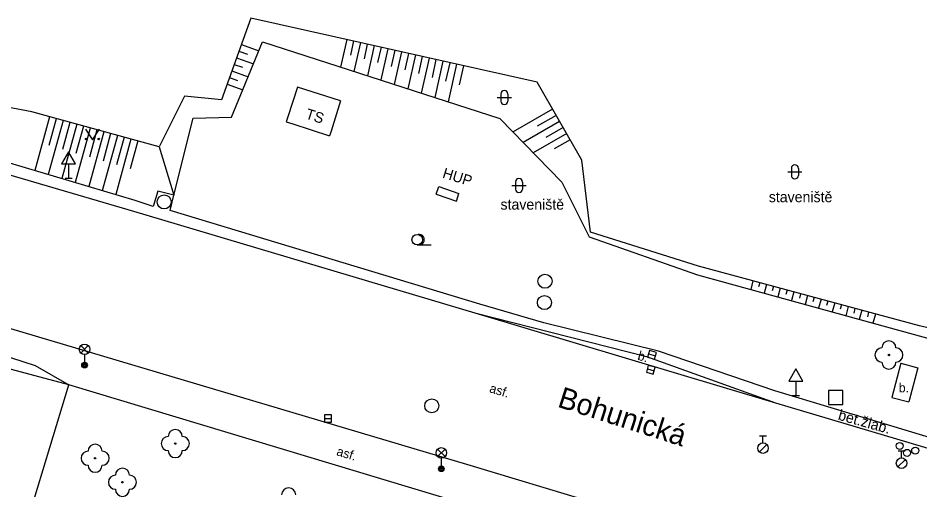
# Model space of a CAD drawing. Extents: x -599951 to -598963, y -1164095 to -1162939.
# Drawn here: x -599671.3 to -599607.3, y -1164057.7 to -1164024.2 of the extents above; entities that cross this region are included whole.
import ezdxf

# ---------------------------------------------------------------- set-up
doc = ezdxf.new("R2010")
doc.units = 0
for name, color, linetype in [('Level 10', 7, 'Continuous'), ('Level 11', 7, 'Continuous'), ('Level 14', 7, 'Continuous'), ('Level 15', 7, 'Continuous'), ('Level 22', 7, 'Continuous'), ('Level 24', 7, 'Continuous'), ('Level 26', 7, 'Continuous'), ('Level 27', 7, 'Continuous'), ('Level 28', 7, 'Continuous'), ('Level 33', 7, 'Continuous'), ('Level 34', 7, 'Continuous'), ('Level 36', 7, 'Continuous'), ('Level 40', 7, 'Continuous'), ('Level 41', 7, 'Continuous'), ('Level 42', 7, 'Continuous'), ('Level 49', 7, 'Continuous'), ('Level 5', 7, 'Continuous'), ('Level 7', 7, 'Continuous')]:
    doc.layers.add(name, color=color, linetype=linetype)

msp = doc.modelspace()

# ---------------------------------------------------------------- linework, layer by layer
at = {"layer": 'Level 10'}
for points in [[(-599677.76, -1164033.65), (-599663.13, -1164037.95), (-599638.89, -1164045.17)], [(-599638.89, -1164045.17), (-599617.56, -1164051.55), (-599596.39, -1164057.85), (-599581.06, -1164062.67), (-599573.37, -1164065.22)], [(-599671.86, -1164046.28), (-599639.5, -1164055.92), (-599621.28, -1164061.4)]]:
    msp.add_lwpolyline(points, dxfattribs=at)
at = {"layer": 'Level 11'}
for points in [[(-599596.35, -1164057.12), (-599617.6, -1164050.7), (-599625.85, -1164047.89), (-599634, -1164045.88), (-599638.54, -1164044.56), (-599660.54, -1164037.91), (-599660.28, -1164036.8), (-599661.4, -1164036.53), (-599661.73, -1164037.61), (-599663.03, -1164037.18), (-599677.51, -1164032.87)], [(-599638.89, -1164045.17), (-599626.72, -1164048.27), (-599617.56, -1164051.55)], [(-599672.71, -1164048.08), (-599670.11, -1164048.9), (-599667.74, -1164050.29)], [(-599608.65, -1164048.75), (-599609.29, -1164051.17)], [(-599608.65, -1164048.75), (-599607.45, -1164049.07)], [(-599607.45, -1164049.07), (-599608.09, -1164051.49)], [(-599639.68, -1164058.74), (-599667.74, -1164050.29)], [(-599609.29, -1164051.17), (-599608.09, -1164051.49)]]:
    msp.add_lwpolyline(points, dxfattribs=at)
at = {"layer": 'Level 14'}
for points in [[(-599587.26, -1164049.45), (-599587.64, -1164047.53), (-599593, -1164047.51), (-599595.2, -1164048.95), (-599607.33, -1164046.09), (-599623.03, -1164041.85), (-599630.68, -1164039.44), (-599631.31, -1164034.32), (-599634.48, -1164028.79), (-599654.8, -1164024.23), (-599656.89, -1164030.03), (-599659.52, -1164029.78), (-599661.32, -1164033.38), (-599670.35, -1164030.9), (-599677.62, -1164029.52), (-599680.115, -1164029.175)], [(-599660.28, -1164036.8), (-599658.89, -1164031.33), (-599656.17, -1164031.26), (-599653.98, -1164025.92), (-599637.13, -1164031.36), (-599632.73, -1164035.88), (-599630.79, -1164039.78), (-599623.09, -1164042.46), (-599606.14, -1164047.14), (-599594.76, -1164050.63), (-599592.29, -1164048.62)], [(-599661.32, -1164033.38), (-599660.28, -1164036.8)]]:
    msp.add_lwpolyline(points, dxfattribs=at)
at = {"layer": 'Level 15'}
for points in [[(-599655.48, -1164026.11), (-599654.24, -1164026.56)], [(-599648, -1164025.76), (-599648.44, -1164027.71)], [(-599647.51, -1164025.86), (-599647.74, -1164026.86)], [(-599647.03, -1164025.97), (-599647.49, -1164028.02)], [(-599646.54, -1164026.08), (-599646.77, -1164027.13)], [(-599646.05, -1164026.19), (-599646.53, -1164028.33)], [(-599655.65, -1164026.58), (-599655.04, -1164026.8)], [(-599645.56, -1164026.3), (-599645.81, -1164027.39)], [(-599645.08, -1164026.41), (-599645.57, -1164028.63)], [(-599644.59, -1164026.52), (-599644.84, -1164027.66)], [(-599644.1, -1164026.63), (-599644.62, -1164028.94)], [(-599643.61, -1164026.74), (-599643.88, -1164027.92)], [(-599643.12, -1164026.85), (-599643.66, -1164029.25)], [(-599655.99, -1164027.52), (-599655.4, -1164027.73)], [(-599655.82, -1164027.05), (-599654.62, -1164027.48)], [(-599642.64, -1164026.96), (-599642.91, -1164028.18)], [(-599642.15, -1164027.07), (-599642.71, -1164029.56)], [(-599641.66, -1164027.18), (-599641.94, -1164028.45)], [(-599641.17, -1164027.29), (-599641.75, -1164029.87)], [(-599640.68, -1164027.4), (-599640.98, -1164028.71)], [(-599640.2, -1164027.51), (-599640.8, -1164030.18)], [(-599656.16, -1164027.99), (-599655, -1164028.41)], [(-599639.71, -1164027.62), (-599640.01, -1164028.97)], [(-599656.33, -1164028.46), (-599655.76, -1164028.67)], [(-599656.49, -1164028.93), (-599655.38, -1164029.34)], [(-599633.38, -1164030.71), (-599636.19, -1164032.32)], [(-599669.1, -1164031.24), (-599670.15, -1164035.06)], [(-599668.62, -1164031.38), (-599669.15, -1164033.29)], [(-599633.13, -1164031.14), (-599634.48, -1164031.92)], [(-599668.14, -1164031.51), (-599669.19, -1164035.35)], [(-599667.17, -1164031.77), (-599668.23, -1164035.63)], [(-599667.66, -1164031.64), (-599668.18, -1164033.56)], [(-599666.69, -1164031.9), (-599667.22, -1164033.84)], [(-599632.88, -1164031.58), (-599635.47, -1164033.06)], [(-599632.63, -1164032.01), (-599633.87, -1164032.72)], [(-599666.21, -1164032.04), (-599667.27, -1164035.92)], [(-599665.24, -1164032.3), (-599666.32, -1164036.2)], [(-599665.73, -1164032.17), (-599666.26, -1164034.11)], [(-599664.28, -1164032.57), (-599665.36, -1164036.49)], [(-599664.76, -1164032.43), (-599665.3, -1164034.39)], [(-599632.38, -1164032.44), (-599634.75, -1164033.8)], [(-599663.32, -1164032.83), (-599664.4, -1164036.77)], [(-599663.8, -1164032.7), (-599664.34, -1164034.66)], [(-599662.83, -1164032.96), (-599663.38, -1164034.94)], [(-599632.14, -1164032.88), (-599633.26, -1164033.53)], [(-599619.15, -1164042.9), (-599619.31, -1164043.5)], [(-599618.66, -1164043.03), (-599618.75, -1164043.33)], [(-599618.18, -1164043.16), (-599618.35, -1164043.77)], [(-599617.7, -1164043.29), (-599617.78, -1164043.6)], [(-599617.22, -1164043.42), (-599617.38, -1164044.04)], [(-599616.73, -1164043.55), (-599616.82, -1164043.86)], [(-599616.25, -1164043.68), (-599616.42, -1164044.3)], [(-599615.77, -1164043.81), (-599615.85, -1164044.12)], [(-599615.28, -1164043.94), (-599615.45, -1164044.57)], [(-599614.8, -1164044.07), (-599614.89, -1164044.39)], [(-599614.32, -1164044.2), (-599614.49, -1164044.83)], [(-599613.84, -1164044.33), (-599613.92, -1164044.65)], [(-599613.35, -1164044.46), (-599613.53, -1164045.1)], [(-599612.87, -1164044.59), (-599612.96, -1164044.91)], [(-599612.39, -1164044.72), (-599612.56, -1164045.37)], [(-599611.91, -1164044.85), (-599611.99, -1164045.18)], [(-599611.42, -1164044.98), (-599611.6, -1164045.63)], [(-599610.94, -1164045.12), (-599611.03, -1164045.44)], [(-599610.46, -1164045.25), (-599610.63, -1164045.9)]]:
    msp.add_lwpolyline(points, dxfattribs=at)
at = {"layer": 'Level 22'}
for centre in [(-599609.5, -1164048.16), (-599660.17, -1164054.45), (-599665.86, -1164055.49), (-599663.92, -1164057.2)]:
    msp.add_circle(centre, 0.05, dxfattribs=at)
for centre, start, end in [((-599609.5, -1164047.66), 0, 180), ((-599610, -1164048.16), 90, 270), ((-599609, -1164048.16), 270, 90), ((-599609.5, -1164048.66), 180, 0), ((-599660.17, -1164053.95), 0, 180), ((-599660.67, -1164054.45), 90, 270), ((-599659.67, -1164054.45), 270, 90), ((-599666.36, -1164055.49), 90, 270), ((-599665.86, -1164054.99), 0, 180), ((-599665.36, -1164055.49), 270, 90), ((-599660.17, -1164054.95), 180, 0), ((-599665.86, -1164055.99), 180, 0), ((-599663.92, -1164056.7), 0, 180), ((-599664.42, -1164057.2), 90, 270), ((-599663.42, -1164057.2), 270, 90), ((-599652.12, -1164058.1), 0, 180), ((-599663.92, -1164057.7), 180, 0)]:
    msp.add_arc(centre, 0.5, start, end, dxfattribs=at)
at = {"layer": 'Level 24'}
for points in [[(-599641.64, -1164036.75), (-599641.45, -1164036.2), (-599640.03, -1164036.68)], [(-599641.64, -1164036.75), (-599640.2, -1164037.23)], [(-599640.2, -1164037.23), (-599640.03, -1164036.68)]]:
    msp.add_lwpolyline(points, dxfattribs=at)
at = {"layer": 'Level 26'}
msp.add_lwpolyline([(-599613.78, -1164051.67), (-599612.78, -1164051.67), (-599612.78, -1164050.67), (-599613.78, -1164050.67)], close=True, dxfattribs=at)
at = {"layer": 'Level 27'}
for p, q in [((-599626.56, -1164048.07), (-599626.08, -1164048.21)), ((-599626.651, -1164049.143), (-599626.169, -1164049.277)), ((-599649.58, -1164052.67), (-599649.08, -1164052.67))]:
    msp.add_line(p, q, dxfattribs=at)
for points in [[(-599626.63, -1164048.309), (-599626.151, -1164048.45), (-599626.01, -1164047.971), (-599626.489, -1164047.83)], [(-599626.718, -1164049.384), (-599626.236, -1164049.518), (-599626.102, -1164049.036), (-599626.584, -1164048.902)], [(-599649.58, -1164052.92), (-599649.08, -1164052.92), (-599649.08, -1164052.42), (-599649.58, -1164052.42)]]:
    msp.add_lwpolyline(points, close=True, dxfattribs=at)
for centre in [(-599660.96, -1164037.29), (-599633.92, -1164042.92), (-599633.96, -1164044.44), (-599641.96, -1164051.77)]:
    msp.add_circle(centre, 0.5, dxfattribs=at)
at = {"layer": 'Level 28'}
for p, q in [((-599618.69, -1164053.895), (-599618.19, -1164053.895)), ((-599618.44, -1164054.395), (-599618.44, -1164053.895)), ((-599618.698, -1164055.042), (-599618.168, -1164054.512)), ((-599608.85, -1164054.965), (-599608.35, -1164054.965)), ((-599608.6, -1164055.465), (-599608.6, -1164054.965)), ((-599608.858, -1164056.112), (-599608.328, -1164055.582))]:
    msp.add_line(p, q, dxfattribs=at)
for centre, radius in [((-599618.44, -1164054.77), 0.375), ((-599608.73, -1164054.62), 0.25), ((-599608.21, -1164055.11), 0.25), ((-599607.63, -1164054.95), 0.25), ((-599608.6, -1164055.84), 0.375)]:
    msp.add_circle(centre, radius, dxfattribs=at)
at = {"layer": 'Level 33'}
for p, q in [((-599666.875, -1164048.02), (-599666.345, -1164047.49)), ((-599666.875, -1164047.49), (-599666.345, -1164048.02)), ((-599666.61, -1164048.13), (-599666.61, -1164048.88)), ((-599641.545, -1164055.38), (-599641.015, -1164054.85)), ((-599641.545, -1164054.85), (-599641.015, -1164055.38)), ((-599641.28, -1164055.49), (-599641.28, -1164056.24))]:
    msp.add_line(p, q, dxfattribs=at)
for centre, radius in [((-599666.61, -1164047.755), 0.375), ((-599666.61, -1164048.88), 0.2), ((-599666.61, -1164048.88), 0.145), ((-599666.61, -1164048.88), 0.0876), ((-599641.28, -1164055.115), 0.375), ((-599641.28, -1164056.24), 0.2), ((-599641.28, -1164056.24), 0.145), ((-599641.28, -1164056.24), 0.0876)]:
    msp.add_circle(centre, radius, dxfattribs=at)
at = {"layer": 'Level 34'}
for p, q in [((-599667.75, -1164034.592), (-599667.75, -1164035.61)), ((-599668, -1164035.61), (-599667.5, -1164035.61)), ((-599616.11, -1164050.012), (-599616.11, -1164051.03)), ((-599616.36, -1164051.03), (-599615.86, -1164051.03))]:
    msp.add_line(p, q, dxfattribs=at)
for points in [[(-599668.25, -1164034.592), (-599667.25, -1164034.592), (-599667.75, -1164033.726)], [(-599616.61, -1164050.012), (-599615.61, -1164050.012), (-599616.11, -1164049.146)]]:
    msp.add_lwpolyline(points, close=True, dxfattribs=at)
at = {"layer": 'Level 36'}
for p, q in [((-599637.306, -1164029.876), (-599636.306, -1164029.876)), ((-599637.056, -1164029.626), (-599637.056, -1164030.126)), ((-599636.556, -1164029.626), (-599636.556, -1164030.126)), ((-599616.676, -1164035.156), (-599615.676, -1164035.156)), ((-599616.426, -1164034.906), (-599616.426, -1164035.406)), ((-599615.926, -1164034.906), (-599615.926, -1164035.406)), ((-599636.266, -1164036.126), (-599635.266, -1164036.126)), ((-599636.016, -1164035.876), (-599636.016, -1164036.376)), ((-599635.516, -1164035.876), (-599635.516, -1164036.376)), ((-599642.99, -1164040.345), (-599641.99, -1164040.345))]:
    msp.add_line(p, q, dxfattribs=at)
msp.add_lwpolyline([(-599666.55, -1164032.12), (-599666.05, -1164032.87), (-599665.55, -1164032.12)], dxfattribs=at)
for centre, radius in [((-599666.5, -1164032.82), 0.05), ((-599665.601, -1164032.82), 0.05), ((-599642.99, -1164039.97), 0.375)]:
    msp.add_circle(centre, radius, dxfattribs=at)
for centre, radius, start, end in [((-599636.806, -1164029.626), 0.25, 0, 180), ((-599636.806, -1164030.126), 0.25, 180, 0), ((-599616.176, -1164034.906), 0.25, 0, 180), ((-599635.766, -1164035.876), 0.25, 0, 180), ((-599616.176, -1164035.406), 0.25, 180, 0), ((-599635.766, -1164036.376), 0.25, 180, 0), ((-599642.865, -1164039.97), 0.375, 260.40593, 99.59407)]:
    msp.add_arc(centre, radius, start, end, dxfattribs=at)
at = {"layer": 'Level 5'}
for points in [[(-599651.49, -1164029.13), (-599652.17, -1164031.24), (-599652.29, -1164031.6)], [(-599648.43, -1164030.12), (-599651.49, -1164029.13)], [(-599648.43, -1164030.12), (-599649.1, -1164032.26), (-599649.21, -1164032.6)], [(-599652.29, -1164031.6), (-599651.82, -1164031.75), (-599649.21, -1164032.6)]]:
    msp.add_lwpolyline(points, dxfattribs=at)
at = {"layer": 'Level 7'}
for points in [[(-599667.74, -1164050.29), (-599673.25, -1164048.82)], [(-599673.61, -1164069.76), (-599670.42, -1164059.17), (-599667.74, -1164050.29)]]:
    msp.add_lwpolyline(points, dxfattribs=at)

# ---------------------------------------------------------------- texts
at = {"layer": 'Level 40'}
for s, rotation, p in [('b.', 343, (-599627.39, -1164048.48)), ('asf.', 343.09, (-599637.91, -1164050.79)), ('asf.', 343.09, (-599648.77, -1164055.27))]:
    msp.add_text(s, height=0.65, rotation=rotation, dxfattribs=at).set_placement(p)
msp.add_text('b.', height=0.65, dxfattribs=at).set_placement((-599608.8, -1164050.81))
at = {"layer": 'Level 41'}
for s, rotation, p in [('TS', 342, (-599650.98, -1164031.35)), ('HUP', 342.93989, (-599641.25, -1164035.56))]:
    msp.add_text(s, height=0.75, rotation=rotation, dxfattribs=at).set_placement(p)
at = {"layer": 'Level 42'}
for p in [(-599637.08, -1164037.84), (-599618.03, -1164037.31)]:
    msp.add_text('staveniště', height=0.75, dxfattribs=at).set_placement(p)
msp.add_text('bet.žlab.', height=0.75, rotation=344.25607, dxfattribs=at).set_placement((-599613.16, -1164052.74))
at = {"layer": 'Level 49'}
msp.add_text('Bohunická ', height=1.5, rotation=342.3, dxfattribs=at).set_placement((-599633.1, -1164051.82))

doc.saveas('drawing.dxf')
